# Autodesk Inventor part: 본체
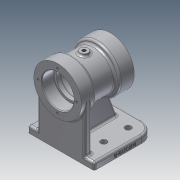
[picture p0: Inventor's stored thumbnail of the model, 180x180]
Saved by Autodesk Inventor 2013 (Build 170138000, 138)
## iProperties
Created: 2020-06
Part Number: 본체
Material: 알루미늄 6061
Document SubType Name: Modeling
Designer: user
Density: 1 g/cm^3
Author: user
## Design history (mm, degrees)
sketch "스케치1"
  geometry: L1 (-39, 0)-(39, 0); L2 (-39, 0)-(-39, 35); L3 (-39, 35)-(-17, 35); L4 (-17, 35)-(-17, 29); L5 (-17, 29)-(17, 29); L6 (17, 29)-(17, 35); L7 (17, 35)-(39, 35); L8 (39, 35)-(39, 0); 2 further points
  constraints: 16 end point, 3 parallel, 3 perpendicular, 1 coincident, 1 collinear, 1 horizontal, 1 midpoint
  dimensions: "d0" = 78 distance of L1.start L1.end; "d1" = 70 diameter of L3 L1; "d2" = 70 diameter of L7 L1; "d3" = 22 distance between parallel lines of L4 L2; "d4" = 22 distance between parallel lines of L8 L6; "d5" = 58 diameter of L5 L1
revolve "회전1" sketch "스케치1" stored, may be unused: angle "d6" = 90 deg
sketch "스케치2"
  geometry: L1 (-39, -35)-(-39, 35) reference; L2 (-39, 35)-(-17, 35) reference; L3 (-17, 35)-(-17, 29) reference; L4 (-17, 29)-(17, 29) reference; L5 (17, 29)-(17, 35) reference; L6 (17, 35)-(39, 35) reference; L7 (39, 35)-(39, -35) reference; L8 (39, -35)-(17, -35) reference; L9 (17, -35)-(17, -29) reference; L10 (17, -29)-(-17, -29) reference; L11 (-17, -29)-(-17, -35) reference; L12 (-17, -35)-(-39, -35) reference; L13 (-39, 0)-(39, 0); L14 (-39, 0)-(-39, 23.5); L15 (-39, 23.5)-(-21, 23.5); L16 (-21, 23.5)-(-21, 20); L17 (-21, 20)-(-15, 20); L18 (-15, 20)-(-15, 23); L19 (-15, 23)-(15, 23); L20 (15, 23)-(15, 20); L21 (15, 20)-(21, 20); L22 (21, 20)-(21, 23.5); L23 (21, 23.5)-(39, 23.5); L24 (39, 23.5)-(39, 0); 1 further point
  constraints: 24 end point, 6 parallel, 4 perpendicular, 2 midpoint, 2 point on line
  dimensions: "d7" = 47 diameter of L23 L13; "d10" = 40 diameter of L21 L13; "d11" = 46 diameter of L19 L13; "d12" = 40 diameter of L17 L13; "d13" = 47 diameter of L15 L13; "d14" = 18 distance between parallel lines of L16 L1; "d15" = 6 distance between parallel lines of L18 L16; "d16" = 30 distance between parallel lines of L20 L18; "d17" = 18 distance between parallel lines of L7 L22
revolve "회전2" sketch "스케치2" stored, may be unused: angle "d18" = 90 deg
node "작업 평면1"
sketch "스케치3"
  geometry: L1 (-39, 35)-(-39, -35) reference; L2 (-34, 49)-(56, 49); L3 (56, 49)-(56, -49); L4 (56, -49)-(-34, -49); L5 (-34, -49)-(-34, 49); 2 further points
  constraints: 8 end point, 2 parallel, 1 horizontal, 1 horizontal alignment, 1 midpoint, 1 perpendicular
  dimensions: "d20" = 90 distance of L3.end L4.end; "d21" = 98 distance of L2.end L3.end; "d22" = 5 distance between parallel lines of L5 L1
extrude "돌출1" join sketch "스케치3" distance "d23" = 10; taper "d24" = 0 deg
sketch "스케치4"
  geometry: L1 (34, -49)-(34, 49) reference; L2 (34, -35)-(24, -35); L3 (24, -35)-(24, 35); L4 (24, 35)-(34, 35); L5 (34, 35)-(34, -35); 4 further points
  constraints: 8 end point, 3 midpoint, 2 parallel, 1 coincident, 1 horizontal, 1 horizontal alignment, 1 perpendicular
  dimensions: "d25" = 10 distance of L3.end L4.end; "d26" = 70 distance of L2.end L3.end
extrude "돌출2" join sketch "스케치4" stored distance "d27" = 10; taper "d28" = 0 deg
sketch "스케치5"
  geometry: L1 (39, 23.5)-(21, 23.5) reference; L2 (21, 23.5)-(21, 20) reference; L3 (21, 20)-(15, 20) reference; L4 (15, 20)-(15, 23) reference; L5 (15, 23)-(-15, 23) reference; L6 (-15, 23)-(-15, 20) reference; L7 (-15, 20)-(-21, 20) reference; L8 (-21, 20)-(-21, 23.5) reference; L9 (-21, 23.5)-(-39, 23.5) reference; L10 (-39, 23.5)-(-39, 35) reference; L11 (-39, 35)-(-17, 35) reference; L12 (-17, 35)-(-17, 29) reference; L13 (-17, 29)-(17, 29) reference; L14 (17, 29)-(17, 35) reference; L15 (17, 35)-(39, 35) reference; L16 (39, 35)-(39, 23.5) reference; L17 (21, -23.5)-(39, -23.5) reference; L18 (39, -23.5)-(39, -35) reference; L19 (39, -35)-(34, -35) reference; L20 (34, -35)-(34, -80) reference; L21 (34, -80)-(-56, -80) reference; L22 (-56, -80)-(-56, -70) reference; L23 (-56, -70)-(24, -70) reference; L24 (24, -70)-(24, -35) reference; L25 (24, -35)-(17, -35) reference; L26 (17, -35)-(17, -29) reference; L27 (17, -29)-(-17, -29) reference; L28 (-17, -29)-(-17, -35) reference; L29 (-17, -35)-(-39, -35) reference; L30 (-39, -35)-(-39, -23.5) reference; L31 (-39, -23.5)-(-21, -23.5) reference; L32 (-21, -23.5)-(-21, -20) reference; L33 (-21, -20)-(-15, -20) reference; L34 (-15, -20)-(-15, -23) reference; L35 (-15, -23)-(15, -23) reference; L36 (15, -23)-(15, -20) reference; L37 (15, -20)-(21, -20) reference; L38 (21, -20)-(21, -23.5) reference; L39 (-31.261, -35)-(-44, -70); 1 further point
  constraints: 2 end point, 2 point on line
  dimensions: "d29" = 12 distance from line of L22 L39.end; "d30" = 70 deg angle of L23 L39
feature "리브1" sketch "스케치5" dims "d31" = 1, "d32" = 10, "d33" = 0, "d34" = 0, "d35" = 1, "d36" = 1
sketch "스케치6"
  geometry: L1 (34, 49)-(34, -49) reference; 5 further points
  constraints: 2 horizontal alignment, 1 vertical alignment
  dimensions: "d37" = 58 distance of point (-36, 29) point (-36, -29); "d39" = 29 vertical distance of point (-36, -29) point (0, 0); "d40" = 29 vertical distance of point (-36, 29) point (0, 0); "d41" = 36 distance of point (-36, -29) point (0, -29); "d42" = 70 distance from line of L1 point (-36, -29)
hole "구멍1" sketch "스케치6" at (-36, -29), (0, -29), (0, 29), (-36, 29) diameter "d43" = 9; stored, may be unused: countersink angle "d47" = 90 deg, drill point angle "d49" = 118 deg; dims "d44" = 6, "d45" = 4, "d46" = 2, "d48" = 8
sketch "스케치7"
  geometry: C1 r 23.5 at (0, 0) reference; C2 r 35 at (0, 0) reference; A1 r 28.5 centre (0, 0) between (0, 28.5) and (28.5, 0); 2 further points
  constraints: 4 point on circle, 2 horizontal alignment, 2 vertical alignment, 1 centre point, 1 coincident
  dimensions: "d50" = 57 diameter of A1
hole "구멍2" sketch "스케치7" at (0, 28.5), (28.5, 0), (0, -28.5), (-28.5, 0) diameter "d51" = 3.242; stored, may be unused: countersink angle "d55" = 90 deg, drill point angle "d57" = 118 deg; dims "d52" = 10, "d53" = 4, "d54" = 2, "d56" = 12
fillet "모깎기1" dims "d58" = 20
fillet "모깎기2" dims "d59" = 0.3
fillet "모깎기3" dims "d60" = 3
chamfer "모따기1" distance "d61" = 1; stored, may be unused: second distance "d62" = 2, angle "d63" = 45 deg
node "작업 평면3"
  node "작업 평면2"
sketch "스케치8"
  geometry: C1 r 6 at (0, 0); 1 further point
  constraints: 1 centre point, 1 coincident
  dimensions: "d65" = 12 diameter of C1
extrude "돌출3" join sketch "스케치8" stored distance "d66" = 10; taper "d67" = 0 deg
sketch "스케치9"
  geometry: C1 r 6 at (0, 0) reference; 1 further point
  constraints: 1 coincident
hole "구멍3" sketch "스케치9" at (0, 0) diameter "d68" = 5.188; stored, may be unused: countersink angle "d72" = 90 deg, drill point angle "d74" = 118 deg; dims "d69" = 10, "d70" = 4, "d71" = 2, "d73" = 12
fillet "모깎기4" dims "d75" = 3
fillet "모깎기5" dims "d76" = 3
fillet "모깎기6" dims "d77" = 3
fillet "모깎기7" dims "d78" = 3
fillet "모깎기8" dims "d79" = 3
fillet "모깎기9" dims "d80" = 3
fillet "모깎기10" dims "d81" = 3
fillet "모깎기11" dims "d82" = 3
sketch "스케치10"
  geometry: L1 (67, 0)-(0, 0) reference; L2 (-3, 7)-(-3, 0) reference; 2 further points
  constraints: 1 other
  dimensions: "d83" = 4 distance from line of L1 point (42, 4); "d84" = 45 distance from line of L2 point (42, 4)
feature "엠보싱1" sketch "스케치10" dims "d0" = 78, "d1" = 70, "d2" = 70, "d3" = 22, "d4" = 22, "d5" = 58, "d7" = 47, "d10" = 40, "d11" = 46, "d12" = 40, "d13" = 47, "d14" = 18, "d15" = 6, "d16" = 30, "d17" = 18, "d85" = 0.5, "d86" = 0
fillet "모깎기12" dims "d87" = 3
node "솔리드1"
mirror "대칭1"
node "절단 모서리 투영1"
node "절단 모서리 투영2"
other parameters: "d64" = 3
